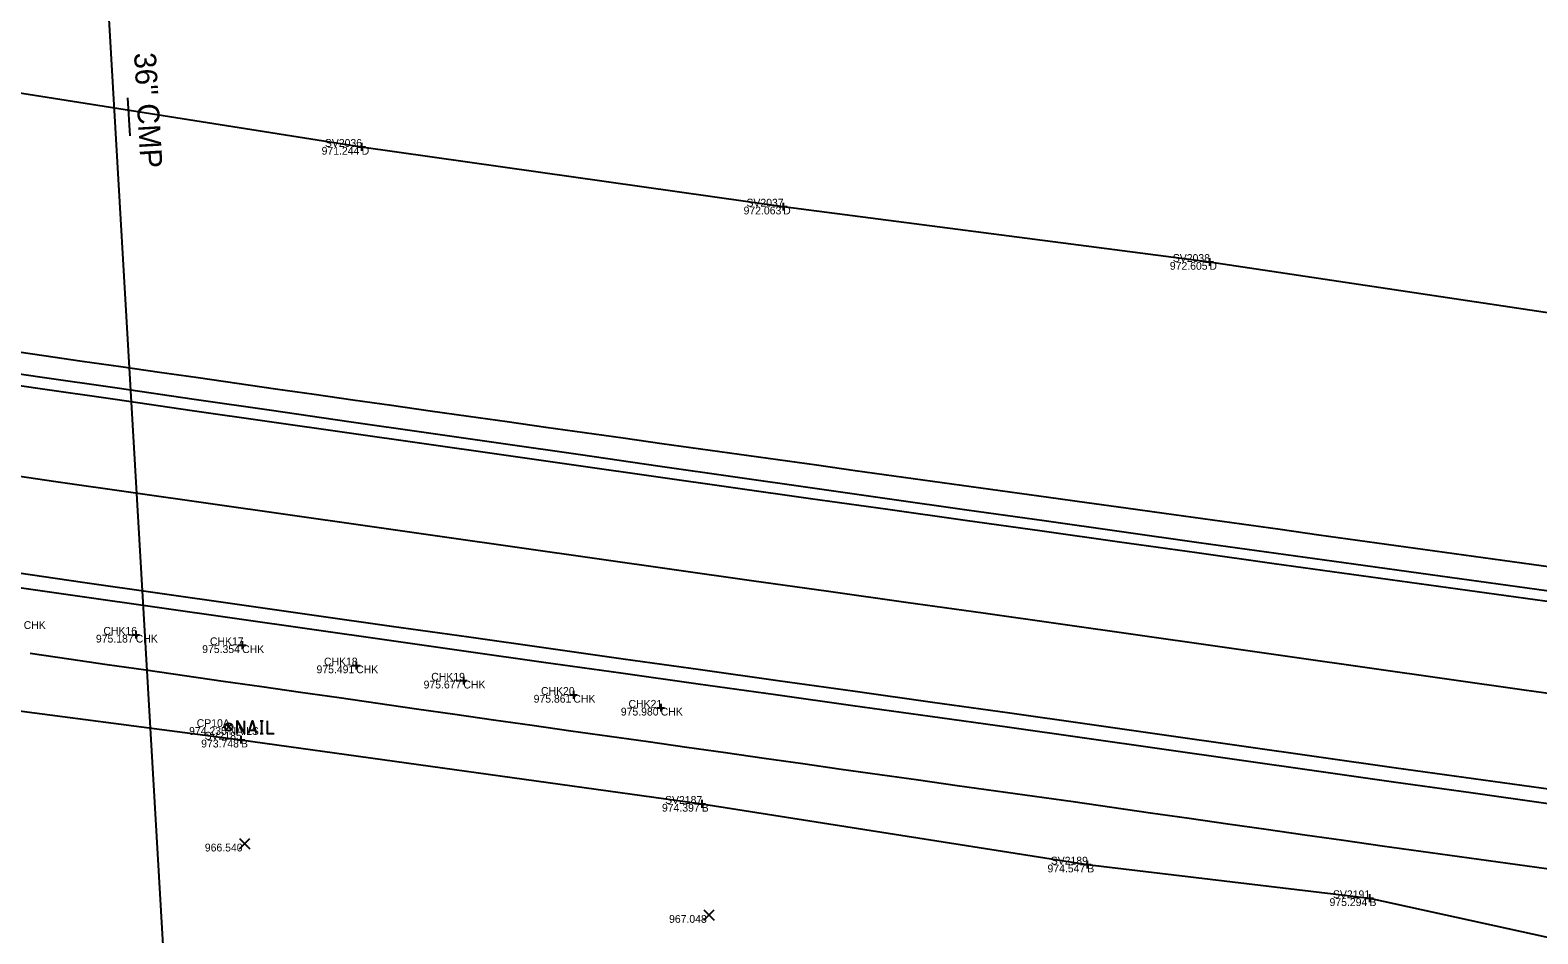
# Model space of a CAD drawing. Extents: x 2065431 to 2068157, y 709104 to 709719.
# Drawn here: x 2066392 to 2066585.2, y 709367.9 to 709483.7 of the extents above; entities that cross this region are included whole.
import ezdxf

# ---------------------------------------------------------------- set-up
doc = ezdxf.new("R2010")
doc.units = 0
for name, color, linetype in [('DR_X_Storm_Sewer', 7, 'Continuous'), ('DR_X_Text', 7, 'Continuous'), ('PM_X_Edge_Line', 7, 'Continuous'), ('PM_X_Lane_Line', 7, 'Continuous'), ('PV_X_EOP', 7, 'Continuous'), ('PV_X_Shoulder_Rumble_Strip', 7, 'Continuous'), ('RS_Raster1', 7, 'Continuous'), ('RW_X_CL_100_Bearings', 7, 'Continuous'), ('RW_X_CL_100_Stations', 7, 'Continuous'), ('RW_X_Fee_WL', 7, 'Continuous'), ('SV_X_Break_Lines', 7, 'Continuous'), ('SV_X_Mon_Cells_Found', 7, 'Continuous'), ('SV_X_Text_Elevation', 7, 'Continuous'), ('SV_X_Text_Name', 7, 'Continuous')]:
    doc.layers.add(name, color=color, linetype=linetype)

msp = doc.modelspace()

# ---------------------------------------------------------------- linework, layer by layer
at = {"layer": 'DR_X_Storm_Sewer'}
msp.add_line((2066393.36, 709634.39), (2066412.21, 709311.61), dxfattribs=at)
at = {"layer": 'DR_X_Text'}
msp.add_line((2066404.8, 709470.18), (2066404.52, 709475.03), dxfattribs=at)
at = {"layer": 'PM_X_Edge_Line'}
for points in [[(2066383.07, 709439.29), (2066392.97, 709437.86), (2066402.87, 709436.43), (2066412.76, 709435), (2066422.66, 709433.58), (2066432.56, 709432.16), (2066442.46, 709430.75), (2066452.36, 709429.34), (2066462.26, 709427.93), (2066472.16, 709426.52), (2066482.06, 709425.13), (2066491.97, 709423.73), (2066501.87, 709422.34), (2066511.77, 709420.95), (2066521.67, 709419.56), (2066531.58, 709418.18), (2066541.48, 709416.79), (2066551.39, 709415.41), (2066561.29, 709414.03), (2066571.19, 709412.65), (2066581.1, 709411.28), (2066591.01, 709409.91)], [(2066388.79, 709414.43), (2066398.69, 709413.01), (2066408.59, 709411.6), (2066418.49, 709410.19), (2066428.39, 709408.78), (2066438.29, 709407.38), (2066448.19, 709405.98), (2066458.09, 709404.58), (2066467.99, 709403.19), (2066477.9, 709401.79), (2066487.8, 709400.41), (2066497.7, 709399.02), (2066507.61, 709397.64), (2066517.51, 709396.26), (2066527.42, 709394.87), (2066537.31, 709393.44), (2066547.21, 709392.03), (2066557.11, 709390.63), (2066567.02, 709389.23), (2066576.92, 709387.84), (2066586.82, 709386.47)]]:
    msp.add_lwpolyline(points, dxfattribs=at)
at = {"layer": 'PM_X_Lane_Line'}
msp.add_lwpolyline([(2066385.4, 709427.34), (2066395.29, 709425.91), (2066405.19, 709424.49), (2066415.09, 709423.07), (2066424.99, 709421.65), (2066434.89, 709420.24), (2066444.79, 709418.83), (2066454.69, 709417.43), (2066464.59, 709416.02), (2066474.49, 709414.63), (2066484.4, 709413.23), (2066494.3, 709411.84), (2066504.2, 709410.45), (2066514.11, 709409.06), (2066524.01, 709407.68), (2066533.91, 709406.27), (2066543.81, 709404.84), (2066553.71, 709403.42), (2066563.61, 709402.01), (2066573.51, 709400.61), (2066583.41, 709399.22), (2066593.31, 709397.84)], dxfattribs=at)
at = {"layer": 'PV_X_EOP'}
for points in [[(2066388.77, 709442.76), (2066393.72, 709442.04), (2066398.67, 709441.33), (2066403.62, 709440.62), (2066408.57, 709439.91), (2066413.52, 709439.2), (2066418.47, 709438.49), (2066423.42, 709437.78), (2066428.37, 709437.07), (2066433.32, 709436.37), (2066438.27, 709435.66), (2066443.22, 709434.96), (2066448.17, 709434.26), (2066453.12, 709433.56), (2066458.07, 709432.86), (2066463.02, 709432.17), (2066467.97, 709431.47), (2066472.93, 709430.78), (2066477.88, 709430.08), (2066482.83, 709429.39), (2066487.78, 709428.7), (2066492.73, 709428.01), (2066497.69, 709427.32), (2066502.64, 709426.64), (2066507.59, 709425.95), (2066512.54, 709425.27), (2066517.5, 709424.58), (2066522.45, 709423.9), (2066527.4, 709423.22), (2066532.36, 709422.53), (2066537.31, 709421.84), (2066542.26, 709421.15), (2066547.21, 709420.46), (2066552.16, 709419.77), (2066557.12, 709419.08), (2066562.07, 709418.39), (2066567.02, 709417.71), (2066571.97, 709417.02), (2066576.93, 709416.34), (2066581.88, 709415.65), (2066586.83, 709414.97)], [(2066391.97, 709403.9), (2066396.92, 709403.18), (2066401.87, 709402.47), (2066406.82, 709401.76), (2066411.77, 709401.05), (2066416.72, 709400.33), (2066421.67, 709399.62), (2066426.62, 709398.92), (2066431.57, 709398.21), (2066436.52, 709397.5), (2066441.47, 709396.79), (2066446.42, 709396.09), (2066451.37, 709395.38), (2066456.32, 709394.67), (2066461.27, 709393.97), (2066466.22, 709393.27), (2066471.17, 709392.57), (2066476.12, 709391.86), (2066481.07, 709391.16), (2066486.02, 709390.46), (2066490.97, 709389.76), (2066495.92, 709389.06), (2066500.87, 709388.37), (2066505.82, 709387.67), (2066510.78, 709386.97), (2066515.73, 709386.28), (2066520.68, 709385.58), (2066525.63, 709384.88), (2066530.58, 709384.16), (2066535.53, 709383.45), (2066540.48, 709382.75), (2066545.43, 709382.04), (2066550.38, 709381.34), (2066555.33, 709380.63), (2066560.28, 709379.93), (2066565.23, 709379.24), (2066570.18, 709378.54), (2066575.13, 709377.85), (2066580.08, 709377.16), (2066585.04, 709376.47), (2066589.99, 709375.79)]]:
    msp.add_lwpolyline(points, dxfattribs=at)
at = {"layer": 'PV_X_Shoulder_Rumble_Strip'}
for points in [[(2066383.33, 709440.75), (2066393.23, 709439.31), (2066403.12, 709437.88), (2066413.02, 709436.45), (2066422.92, 709435.02), (2066432.82, 709433.6), (2066442.71, 709432.17), (2066452.61, 709430.75), (2066462.51, 709429.34), (2066472.41, 709427.92), (2066482.31, 709426.51), (2066492.21, 709425.09), (2066502.11, 709423.69), (2066512.01, 709422.28), (2066521.91, 709420.88), (2066531.81, 709419.48), (2066541.72, 709418.1), (2066551.62, 709416.73), (2066561.53, 709415.36), (2066571.43, 709413.99), (2066581.34, 709412.62), (2066591.25, 709411.26)], [(2066388.47, 709412.62), (2066398.37, 709411.2), (2066408.27, 709409.79), (2066418.17, 709408.38), (2066428.07, 709406.98), (2066437.97, 709405.57), (2066447.87, 709404.17), (2066457.77, 709402.77), (2066467.67, 709401.38), (2066477.58, 709399.99), (2066487.48, 709398.6), (2066497.38, 709397.21), (2066507.29, 709395.83), (2066517.19, 709394.45), (2066527.09, 709393.06), (2066536.99, 709391.64), (2066546.89, 709390.22), (2066556.79, 709388.82), (2066566.69, 709387.42), (2066576.6, 709386.04), (2066586.5, 709384.66)]]:
    msp.add_lwpolyline(points, dxfattribs=at)
at = {"layer": 'RS_Raster1'}
for p, q in [((2066433.96, 709468.76), (2066434.96, 709468.76)), ((2066434.46, 709469.26), (2066434.46, 709468.26)), ((2066434.46, 709468.76), (2066434.46, 709468.76)), ((2066487.97, 709461.11), (2066488.97, 709461.11)), ((2066488.47, 709461.61), (2066488.47, 709460.61)), ((2066488.47, 709461.11), (2066488.47, 709461.11)), ((2066542.59, 709454.02), (2066543.59, 709454.02)), ((2066543.09, 709454.52), (2066543.09, 709453.52)), ((2066543.09, 709454.02), (2066543.09, 709454.02)), ((2066405.01, 709406.26), (2066406.01, 709406.26)), ((2066405.51, 709406.76), (2066405.51, 709405.76)), ((2066405.51, 709406.26), (2066405.51, 709406.26)), ((2066418.65, 709404.92), (2066419.65, 709404.92)), ((2066419.15, 709405.42), (2066419.15, 709404.42)), ((2066419.15, 709404.92), (2066419.15, 709404.92)), ((2066433.76, 709402.83), (2066433.76, 709401.83)), ((2066433.26, 709402.33), (2066434.26, 709402.33)), ((2066433.76, 709402.33), (2066433.76, 709402.33)), ((2066447.5, 709400.88), (2066447.5, 709399.88)), ((2066447, 709400.38), (2066448, 709400.38)), ((2066447.5, 709400.38), (2066447.5, 709400.38)), ((2066461.09, 709398.56), (2066462.09, 709398.56)), ((2066461.59, 709399.06), (2066461.59, 709398.06)), ((2066461.59, 709398.56), (2066461.59, 709398.56)), ((2066472.28, 709396.91), (2066473.28, 709396.91)), ((2066472.78, 709397.41), (2066472.78, 709396.41)), ((2066472.78, 709396.91), (2066472.78, 709396.91)), ((2066418.5, 709392.82), (2066419.5, 709392.82)), ((2066419, 709393.32), (2066419, 709392.32)), ((2066419, 709392.82), (2066419, 709392.82)), ((2066478.03, 709385.1), (2066478.03, 709384.1)), ((2066477.53, 709384.6), (2066478.53, 709384.6)), ((2066478.03, 709384.6), (2066478.03, 709384.6)), ((2066527.44, 709377.32), (2066527.44, 709376.32)), ((2066526.94, 709376.82), (2066527.94, 709376.82)), ((2066527.44, 709376.82), (2066527.44, 709376.82)), ((2066563.1, 709372.51), (2066564.1, 709372.51)), ((2066563.6, 709373.01), (2066563.6, 709372.01)), ((2066563.6, 709372.51), (2066563.6, 709372.51))]:
    msp.add_line(p, q, dxfattribs=at)
at = {"layer": 'RW_X_CL_100_Bearings'}
for p, q in [((2066418.81, 709378.83), (2066420.15, 709380.17)), ((2066418.81, 709380.17), (2066420.15, 709378.83)), ((2066478.29, 709369.7), (2066479.62, 709371.03)), ((2066478.29, 709371.03), (2066479.62, 709369.7))]:
    msp.add_line(p, q, dxfattribs=at)
at = {"layer": 'RW_X_CL_100_Stations'}
for p, q in [((2066417.07, 709394.79), (2066417.78, 709394.08)), ((2066417.07, 709394.08), (2066417.78, 709394.79))]:
    msp.add_line(p, q, dxfattribs=at)
for points in [[(2066418.51, 709393.63), (2066418.51, 709395.23), (2066419.46, 709393.63), (2066419.46, 709395.23)], [(2066419.96, 709393.63), (2066420.47, 709395.23), (2066420.96, 709393.63)], [(2066421.46, 709395.23), (2066421.86, 709395.23)], [(2066421.66, 709393.63), (2066421.66, 709395.23)], [(2066422.37, 709395.23), (2066422.37, 709393.63), (2066423.24, 709393.63)], [(2066420.83, 709394.01), (2066420.09, 709394.01)], [(2066421.46, 709393.63), (2066421.86, 709393.63)]]:
    msp.add_lwpolyline(points, dxfattribs=at)
msp.add_circle((2066417.42, 709394.44), 0.5, dxfattribs=at)
at = {"layer": 'RW_X_Fee_WL'}
msp.add_lwpolyline([(2066146.22, 709516.28), (2066201.46, 709507.43), (2066256.41, 709499.89), (2066309.66, 709487.73), (2066371.95, 709478.62), (2066434.46, 709468.76), (2066488.47, 709461.11), (2066543.09, 709454.02), (2066597.26, 709445.92), (2066653.85, 709437.6), (2066711.8, 709429.8), (2066769.12, 709422.19), (2066823.53, 709415.48), (2066878.43, 709408.48), (2066947.7, 709399.97)], dxfattribs=at)
at = {"layer": 'SV_X_Break_Lines'}
msp.add_lwpolyline([(2066296.29, 709410.91), (2066340.48, 709404.99), (2066380.77, 709397.8), (2066419, 709392.82), (2066478.03, 709384.6), (2066527.44, 709376.82), (2066563.6, 709372.51), (2066611.9, 709361.92)], dxfattribs=at)

# ---------------------------------------------------------------- texts
at = {"layer": 'DR_X_Text'}
msp.add_text('36" CMP', height=2.8, rotation=273.3419, dxfattribs=at).set_placement((2066405.29, 709480.78))
at = {"layer": 'SV_X_Mon_Cells_Found'}
for s, p in [('SV2036', (2066429.75, 709468.76)), ('SV2037', (2066483.77, 709461.11)), ('SV2038', (2066538.4, 709454.02)), ('CHK16', (2066401.37, 709406.26)), ('CHK17', (2066415.02, 709404.92)), ('CHK18', (2066429.63, 709402.33)), ('CHK19', (2066443.38, 709400.38)), ('CHK20', (2066457.44, 709398.56)), ('CHK21', (2066468.66, 709396.91)), ('CP10A', (2066413.33, 709394.44)), ('SV2185', (2066414.34, 709392.82)), ('SV2187', (2066473.34, 709384.6)), ('SV2189', (2066522.76, 709376.82)), ('SV2191', (2066558.92, 709372.51))]:
    msp.add_text(s, height=1, dxfattribs=at).set_placement(p)
at = {"layer": 'SV_X_Text_Elevation'}
for s, p in [('D', (2066434.46, 709467.76)), ('D', (2066488.47, 709460.11)), ('D', (2066543.09, 709453.02)), ('CHK', (2066391.16, 709407)), ('CHK', (2066405.51, 709405.26)), ('CHK', (2066419.15, 709403.92)), ('CHK', (2066433.76, 709401.33)), ('CHK', (2066447.5, 709399.38)), ('CHK', (2066461.59, 709397.56)), ('CHK', (2066472.78, 709395.91)), ('NAILS', (2066417.42, 709393.44)), ('B', (2066419, 709391.82)), ('B', (2066478.03, 709383.6)), ('B', (2066527.44, 709375.82)), ('B', (2066563.6, 709371.51))]:
    msp.add_text(s, height=1, dxfattribs=at).set_placement(p)
at = {"layer": 'SV_X_Text_Name'}
for s, p in [('971.244', (2066429.33, 709467.76)), ('972.063', (2066483.4, 709460.11)), ('972.605', (2066538.02, 709453.02)), ('975.187', (2066400.41, 709405.26)), ('975.354', (2066414.03, 709403.92)), ('975.491', (2066428.68, 709401.33)), ('975.677', (2066442.4, 709399.38)), ('975.861', (2066456.5, 709397.56)), ('975.980', (2066467.67, 709395.91)), ('974.235', (2066412.35, 709393.44)), ('973.748', (2066413.9, 709391.82)), ('974.397', (2066472.94, 709383.6)), ('966.540', (2066414.37, 709378.5)), ('974.547', (2066522.34, 709375.82)), ('975.294', (2066558.48, 709371.51)), ('967.048', (2066473.85, 709369.36))]:
    msp.add_text(s, height=1, dxfattribs=at).set_placement(p)

doc.saveas('drawing.dxf')
